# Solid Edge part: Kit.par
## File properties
Sűrűség: 0,000 kg/m^3
Pontosság: 0,990
Author: bmolnar
Last saved by: bmolnar
Revision: 76
Username: bmolnar
Dokumentum tartalom típus: 0
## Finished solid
Body 1: solid body, 25 faces, 38 edges, 28 vertices.
  Faces by surface: plane 9, cylinder 8, torus 6, cone 1, spun 1
  Edges by curve: circle 22, line 10, curve on surface 3, ellipse 3
Bounding box of the edges (mm; curved faces can reach further): 14.800 x 14.250 x 2.452, from (-7.4, -6.85, 33.9478) to (7.4, 7.4, 36.4).
Cylindrical faces by radius (mm): R3 x1, R4.6686 x2, R4.675 x1, R5.6 x1, R6.1 x1, R6.85 x1, R7.4 x1
Conical faces (half-angle, radius in mm at the cone's reference point): 45 deg R5.45 x1
Toroidal faces (ring radius, tube radius in mm): R3.4833 r1.1917 x2, R4.0606 r1.0588 x1, R4.475 r0.2 x2, R5.8 r0.2 x1
Planar faces by outward normal: +z 3, -z 4, oblique 2
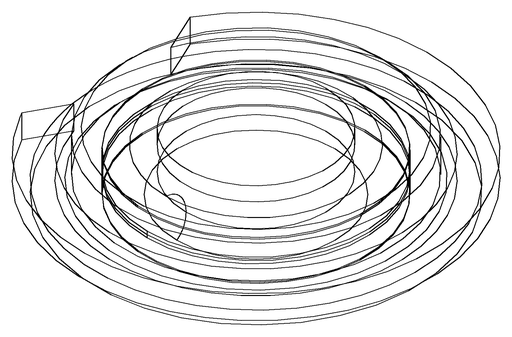
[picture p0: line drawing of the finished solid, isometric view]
